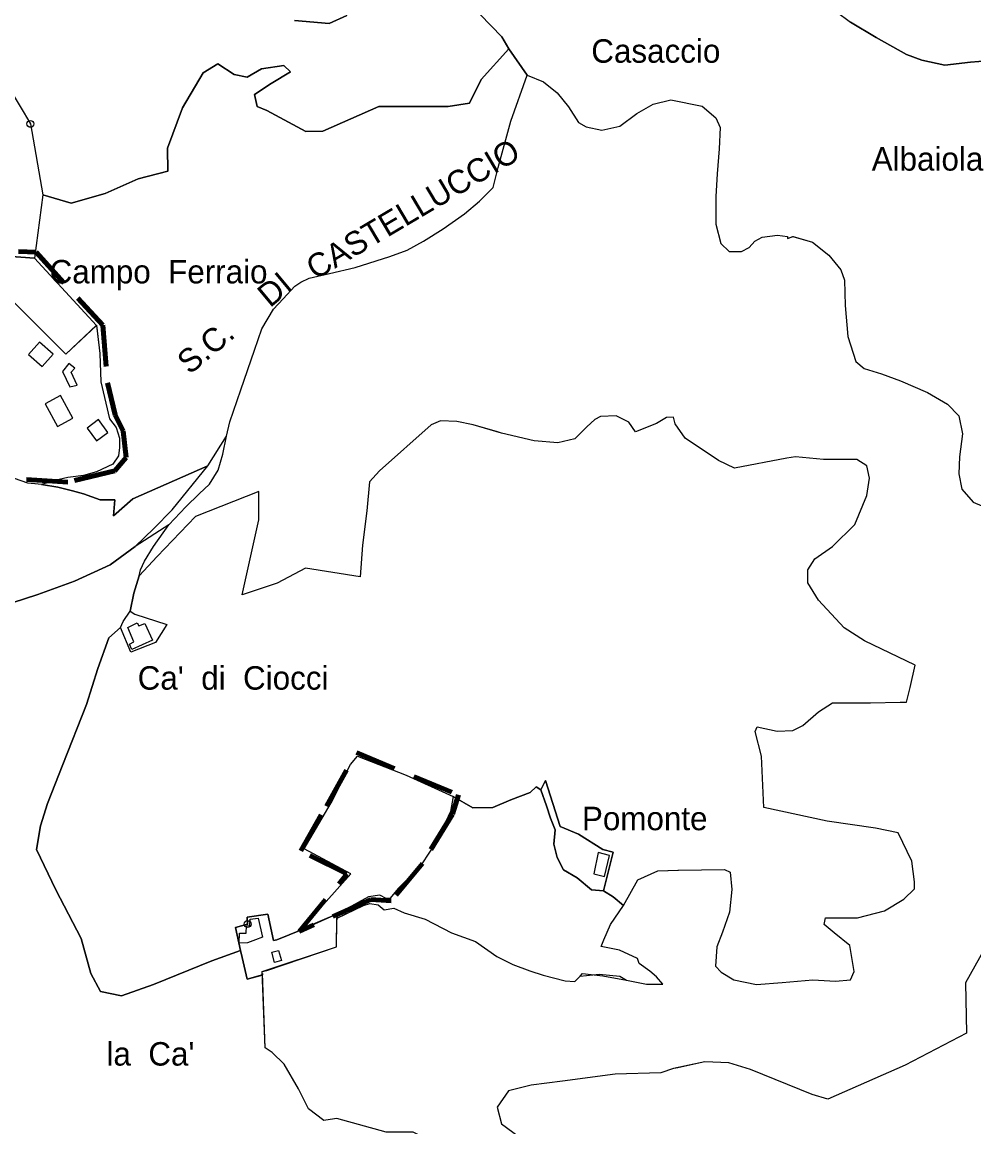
# Model space of a CAD drawing. Extents: x 645880 to 658994, y 884400 to 894744.
# Drawn here: x 654553 to 655242, y 890509 to 891309 of the extents above; entities that cross this region are included whole.
import ezdxf
from ezdxf.enums import TextEntityAlignment as Align

# ---------------------------------------------------------------- set-up
doc = ezdxf.new("R2010")
doc.units = 0
doc.header["$LTSCALE"] = 10
doc.header["$PDMODE"] = 32
doc.header["$PDSIZE"] = 5
doc.linetypes.add('MEDIUM_DASHED', pattern=[4.5, 3, -1.5])
for name, color, linetype, lineweight in [('15', 7, 'MEDIUM_DASHED', 100), ('16', 7, 'Continuous', 25), ('17', 7, 'Continuous', 25), ('18', 7, 'Continuous', 25), ('2', 7, 'Continuous', 25), ('3', 7, 'Continuous', 25), ('30', 7, 'Continuous', 25), ('4', 7, 'Continuous', 25), ('7', 7, 'Continuous', 25), ('8', 7, 'Continuous', 25)]:
    doc.layers.add(name, color=color, linetype=linetype, lineweight=lineweight)
doc.layers.add('60', color=7, linetype='Continuous')

msp = doc.modelspace()

# ---------------------------------------------------------------- linework, layer by layer
at = {"layer": '15'}
msp.add_lwpolyline([(654505.1, 891145.4), (654562.68, 891142.53), (654611.14, 891089.57), (654614.38, 891047.92), (654619.93, 891024.78), (654625.94, 891012.74), (654627.9, 890993.78), (654619.79, 890984.06), (654585.76, 890975.95), (654538.33, 890978.79)], dxfattribs=at)
msp.add_lwpolyline([(654794.8, 890779.81), (654868.71, 890749.12), (654864.4, 890735.17), (654842.78, 890699.57), (654820, 890672.35), (654805.2, 890673.29), (654753.25, 890650.2), (654787.88, 890691.88), (654754.49, 890708.59), (654773.07, 890741.05)], close=True, dxfattribs=at)
at = {"layer": '16'}
for p, q in [((655239.85, 891280.32), (655221.19, 891278.25)), ((655055.24, 891239.99), (655058.34, 891232.99)), ((655056.27, 891199.48), (655055.24, 891182.98)), ((655058.85, 891148.98), (655065.04, 891142.98)), ((655125.23, 891149.86), (655137.09, 891140.36)), ((655137.08, 891140.36), (655145.84, 891129.86)), ((655145.85, 891129.86), (655148.43, 891122.36))]:
    msp.add_line(p, q, dxfattribs=at)
for points in [[(655164.06, 891433.48), (655158.92, 891426.56), (655159.27, 891416.79), (655159.98, 891403.66), (655161.58, 891396.56), (655158.92, 891390.88), (655152.78, 891382.66), (655147.26, 891373.67), (655141.04, 891363.3), (655136.19, 891352.92), (655134.81, 891332.18), (655136.88, 891323.88), (655142.41, 891316.97), (655152.78, 891309.36), (655171.44, 891298.3), (655193.55, 891285.85), (655204.61, 891281.71), (655221.19, 891278.25), (655239.85, 891280.32), (655257.81, 891281.71)], [(654750.02, 891310.44), (654775.04, 891308.28), (654787.79, 891314.04)], [(654884.53, 891314.79), (654900.33, 891298.77), (654905.34, 891290.03), (654918.64, 891270.99)], [(655193.55, 891285.85), (655171.44, 891298.3), (655152.78, 891309.36)], [(655221.19, 891278.25), (655204.61, 891281.71), (655193.55, 891285.86)], [(655270.05, 891275.86), (655278.72, 891277.92), (655257.82, 891281.71), (655239.85, 891280.33)], [(654918.63, 891270.99), (654930.49, 891265.99), (654940.28, 891257.99), (654948.53, 891247.99), (654955.75, 891236.49), (654961.42, 891233.49), (654972.76, 891230.99), (654985.64, 891233.99), (654998.02, 891242.99), (655009.87, 891249.99), (655022.76, 891252.99), (655045.44, 891248.49), (655055.23, 891239.99)], [(655058.33, 891232.99), (655057.81, 891217.49), (655056.26, 891199.48)], [(655055.23, 891182.98), (655055.23, 891162.98), (655058.84, 891148.98)], [(655065.03, 891142.98), (655073.79, 891142.98), (655079.46, 891145.98), (655083.58, 891150.48), (655088.74, 891153.48), (655100.08, 891154.98), (655107.2, 891153.87), (655107.24, 891152.46)], [(655107.25, 891152.46), (655111.2, 891153.99), (655125.23, 891149.86)], [(655148.42, 891122.36), (655148.93, 891103.85), (655150.99, 891081.35), (655156.66, 891063.34), (655162.85, 891058.34), (655175.22, 891054.34), (655189.14, 891049.34), (655208.73, 891040.84), (655223.17, 891032.34), (655231.41, 891023.84), (655233.99, 891010.83), (655231.93, 890994.33), (655231.41, 890981.83), (655233.48, 890970.83), (655241.73, 890961.33), (655257.19, 890954.82)], [(655113.12, 890994.3), (655106.8, 890993.37), (655068.73, 890986.12), (655057.28, 890991.55), (655033.16, 891007.85), (655025.93, 891018.11), (655024.72, 891022.93), (655019.57, 891022.86), (655012.35, 891018.36), (654997.14, 891012.35), (654992.3, 891019.4), (654983.02, 891023.9), (654971.68, 891023.4), (654967.56, 891021.4), (654961.89, 891015.9), (654953.12, 891007.4), (654940.75, 891004.4), (654923.74, 891005.9), (654900.03, 891011.4), (654897.08, 891012.26), (654879.41, 891017.4), (654867.55, 891019.9), (654855.7, 891020.4), (654849, 891017.4), (654811.63, 890984.15), (654804.41, 890976.15), (654802.35, 890955.14), (654799.26, 890930.14), (654797.48, 890907.3), (654757.9, 890913.55), (654737.4, 890902.69), (654712.08, 890894.24), (654724.14, 890948.56), (654724.14, 890969.08), (654678.31, 890950.97), (654650.58, 890922), (654637.48, 890907.88), (654633.67, 890895.42), (654630.79, 890882.47), (654634.36, 890880.23)], [(655197.2, 890701.14), (655187.41, 890721.64), (655170.91, 890725.14), (655135.86, 890730.14), (655089.98, 890740.14), (655088.44, 890777.14), (655083.8, 890795.15), (655085.28, 890798.45), (655099.71, 890795.45), (655111.05, 890795.95), (655118.27, 890799.45), (655129.61, 890809.45), (655139.92, 890815.95), (655167.24, 890815.95), (655188.89, 890816.45), (655193.53, 890816.45), (655196.11, 890826.95), (655199.72, 890843.28), (655163.12, 890860.78), (655148.17, 890870.28), (655129.61, 890890.29), (655121.88, 890902.79), (655121.88, 890912.29), (655127.03, 890920.29), (655139.92, 890929.29), (655155.9, 890945.29), (655164.66, 890966.3), (655166.73, 890978.8), (655164.66, 890987.8), (655157.45, 890992.3), (655148.17, 890992.3), (655133.22, 890992.3), (655113.12, 890994.3)], [(654659.02, 890945), (654634.42, 890929.27), (654616.49, 890915.96), (654590.58, 890904), (654564.01, 890894.36), (654545.41, 890888.38), (654525.81, 890881.73)], [(654630.79, 890882.47), (654633.67, 890895.42), (654637.48, 890907.88), (654638.33, 890912.42), (654641.33, 890918.53), (654647.92, 890929.29), (654659.02, 890945)], [(654710.89, 890636.37), (654690.19, 890628.81), (654647.8, 890611.64), (654624.58, 890603.56), (654609.44, 890606.59), (654602.38, 890619.72), (654595.31, 890644.97), (654577.15, 890680.32), (654563.02, 890709.6), (654566.04, 890726.77), (654571.09, 890742.93), (654582.19, 890771.21), (654599.35, 890814.63), (654607.43, 890840.89), (654615.5, 890863.1), (654623.81, 890870.61), (654625.79, 890874.88), (654630.79, 890882.47)], [(654634.36, 890880.23), (654657.35, 890872.73), (654649.35, 890859.72), (654631.37, 890852.72), (654623.81, 890870.61)], [(654623.81, 890870.61), (654615.5, 890863.1), (654607.43, 890840.89), (654599.35, 890814.63), (654582.19, 890771.21), (654571.09, 890742.93), (654566.04, 890726.77), (654563.02, 890709.6)], [(654790.56, 890771.3), (654795.65, 890777.25), (654830.98, 890763.4), (654864.93, 890747.95)], [(654755.13, 890651.77), (654790.78, 890692.08), (654756.97, 890710.19), (654776.6, 890743.36), (654790.56, 890771.3)], [(654920.82, 890751.04), (654925.17, 890755.02), (654928.59, 890752.77), (654931.89, 890759.67), (654942.38, 890726.17), (654955.87, 890720.67), (654973.39, 890709.56), (654980.89, 890707.55), (654973.86, 890679.66), (654980.82, 890675.37), (654988.43, 890669.13), (654998.74, 890687.63), (655013.18, 890694.13), (655027.82, 890694.62), (655028.12, 890694.63), (655061.63, 890695.13), (655065.75, 890693.13), (655066.79, 890680.63), (655065.24, 890664.13), (655060.08, 890649.63), (655055.96, 890639.13), (655054.93, 890625.13), (655059.05, 890620.63), (655068.33, 890615.13), (655084.83, 890611.63), (655103.38, 890613.13), (655125.55, 890615.13), (655142.04, 890614.13), (655152.87, 890615.13), (655155.45, 890621.13), (655152.35, 890640.13), (655141.01, 890649.13), (655133.8, 890655.13), (655134.83, 890660.13), (655158.02, 890660.13), (655177.61, 890665.13), (655191.53, 890673.63), (655199.26, 890681.13), (655199.26, 890686.13), (655197.2, 890701.14)], [(654864.93, 890747.95), (654863.01, 890737.12), (654856.42, 890723.07), (654849.23, 890709.76), (654840.28, 890696.23), (654825.02, 890681.39)], [(654928.59, 890752.77), (654925.17, 890755.02), (654920.82, 890751.04), (654906.7, 890745.6), (654893.66, 890740.16), (654879.17, 890739.8), (654864.93, 890747.95)], [(654864.93, 890747.95), (654879.17, 890739.8), (654893.66, 890740.16), (654906.7, 890745.6), (654920.82, 890751.04)], [(654988.43, 890669.13), (654980.82, 890675.37), (654973.86, 890679.66), (654965.07, 890680.35), (654954.82, 890689.1), (654944.87, 890694.83), (654940.35, 890703.88), (654937.94, 890713.54), (654938.84, 890723.8), (654935.53, 890732.25), (654932.51, 890741.3), (654928.59, 890752.77)], [(654563.02, 890709.6), (654577.15, 890680.32), (654595.31, 890644.97)], [(654825.02, 890681.39), (654819.29, 890674.44), (654819.29, 890674.44), (654816.36, 890674.07), (654816.36, 890674.07), (654816.36, 890674.07), (654816.36, 890674.07), (654811.86, 890676.4), (654803.55, 890675.31), (654781.19, 890663.07), (654780.94, 890659.9), (654799.86, 890669.07), (654804.54, 890670.44), (654810.54, 890669.57), (654815.04, 890665.78), (654821.93, 890666.96), (654829.47, 890663.64), (654844.54, 890659.11), (654863.83, 890649.15)], [(654863.83, 890649.15), (654881.02, 890642.82), (654896.65, 890631.98), (654897.08, 890631.77), (654908.08, 890626.26), (654908.1, 890626.25), (654920.46, 890621.72), (654930.11, 890618.4), (654946.09, 890614.48), (654953.02, 890613.88), (654956.94, 890617.8), (654958.75, 890619.61), (654973.5, 890618.11), (654990.63, 890614.8), (655005.1, 890612.08), (655016.86, 890612.08), (655012.33, 890617.21), (655007.51, 890621.44), (654999.67, 890626.87), (654998.47, 890630.49), (654985.5, 890636.53), (654972.24, 890639.24), (654974.05, 890644.07), (654978.87, 890655.24), (654988.43, 890669.13)], [(654647.8, 890611.64), (654690.19, 890628.81), (654710.87, 890636.36), (654707.15, 890652.98), (654716, 890655.49), (654715.63, 890660.5), (654730.66, 890662.69), (654734.86, 890643.59), (654737.18, 890644.15), (654755.16, 890651.37), (654774.25, 890659.95), (654781.19, 890663.07), (654755.13, 890651.77)], [(654595.31, 890644.97), (654602.38, 890619.72), (654609.44, 890606.59)], [(654972.05, 890449.74), (654960.71, 890438.74), (654933.91, 890430.74), (654919.47, 890440.74), (654899.88, 890442.74), (654882.36, 890444.74), (654866.89, 890454.74), (654851.43, 890474.74), (654846.27, 890499.75), (654835.96, 890504.75), (654816.38, 890504.75), (654780.74, 890514.57), (654775.74, 890513.89), (654771.32, 890513.15), (654760.15, 890521.7), (654752.92, 890536.17), (654742.41, 890553.92), (654733.87, 890562.47), (654728.62, 890565.76), (654726.69, 890619.72), (654726.69, 890618.67), (654715.69, 890615.67), (654711.99, 890631.37), (654710.89, 890636.37)], [(655253.17, 890643.11), (655236.29, 890612.93), (655236.93, 890576.38), (655192.43, 890553.3), (655136.39, 890528.56), (655125, 890531.94), (655080.38, 890550.04), (655064.71, 890554.87), (655047.31, 890555.75), (655027.82, 890551.45), (655024.87, 890550.8), (655024.63, 890550.75), (655015.35, 890547.75), (654982.36, 890546.75), (654944.21, 890541.75), (654921.53, 890538.75), (654905.04, 890534.75), (654896.79, 890522.75), (654899.88, 890510.75), (654916.38, 890498.75), (654935.97, 890489.75), (654953.49, 890476.74), (654966.9, 890460.74), (654972.05, 890449.74)], [(654609.44, 890606.59), (654624.58, 890603.56), (654647.8, 890611.64)]]:
    msp.add_lwpolyline(points, dxfattribs=at)
at = {"layer": '17'}
for points in [[(654618.78, 890951.44), (654632.76, 890963.84), (654687.23, 890987.78), (654700.71, 891009.29), (654703.03, 891019.55), (654711.13, 891042.82), (654721.02, 891071.62), (654726.42, 891087.04), (654734.82, 891101.29), (654741.72, 891108.86), (654750.11, 891117.88), (654754.61, 891120.79), (654760.61, 891123.69), (654775.3, 891127.19), (654793.89, 891131.48), (654819.14, 891139.48), (654831.52, 891143.98), (654843.37, 891150.48), (654857.81, 891159.48), (654873.27, 891170.48), (654884.09, 891179.48), (654893.89, 891189.48), (654897.5, 891203.98), (654906.78, 891237.49), (654918.63, 891270.99), (654905.34, 891290.03), (654885.3, 891267.67), (654876.78, 891250.5), (654861.25, 891248.23), (654821.17, 891248.23), (654811.15, 891248.23), (654770.51, 891230.24), (654758.26, 891229.99), (654729.98, 891245.31), (654722.97, 891248.23), (654720.96, 891256.97), (654732.99, 891264.75), (654747.01, 891273.27), (654742.26, 891278.02), (654725.97, 891275.44)], [(654725.97, 891275.44), (654715.76, 891269.51), (654706.26, 891271.27), (654694.51, 891279.02), (654683.89, 891272.53), (654668.86, 891247.25), (654657.83, 891218.09), (654658.25, 891201.21), (654636.79, 891195.73), (654612.74, 891185.04), (654588.25, 891178.19), (654567.65, 891184.07), (654561.56, 891138.28), (654606.47, 891089.55)], [(654606.47, 891089.55), (654608.81, 891069.11), (654609.6, 891048.6), (654616.01, 891021.7), (654620.66, 891015.42), (654623.21, 891007.73)], [(654623.21, 891007.73), (654623.21, 891001), (654622.44, 890995.01), (654618.32, 890989.02), (654606.51, 890983.48), (654597, 890980.74), (654585.68, 890979.24), (654577.17, 890977.29), (654566.65, 890974.25)], [(654564.01, 890894.36), (654590.58, 890904), (654616.49, 890915.96), (654634.42, 890929.27), (654648.04, 890942.23), (654661.33, 890955.86), (654687.23, 890987.78), (654632.76, 890963.84), (654618.78, 890951.44)], [(654618.78, 890951.44), (654619.87, 890963.09), (654609.15, 890963.09), (654596.96, 890967.45), (654589.14, 890969.64), (654578.59, 890972.18), (654566.65, 890974.25), (654556.73, 890975.16), (654547.16, 890978.61)], [(654566.65, 890974.25), (654578.59, 890972.18), (654589.14, 890969.64), (654596.96, 890967.45), (654609.15, 890963.09), (654619.87, 890963.09), (654618.78, 890951.44)], [(654463.65, 890829.7), (654487.17, 890857.21), (654491.14, 890861.52), (654498.61, 890867.81), (654506.8, 890873.26), (654523.46, 890881.28), (654545.41, 890888.38), (654564.01, 890894.36)]]:
    msp.add_lwpolyline(points, dxfattribs=at)
at = {"layer": '18'}
for points in [[(654558.82, 891422.97), (654547.79, 891403.53), (654543.78, 891387.98), (654539.99, 891369.33), (654535.77, 891360.76), (654522.74, 891368.54), (654511.72, 891380.2), (654494.99, 891387.59), (654458.99, 891391.09), (654462.99, 891383.59), (654465.62, 891367.56), (654472.64, 891339.37), (654480.74, 891328.55), (654495.69, 891321.87), (654509.71, 891295.63), (654520.55, 891274.47), (654543.6, 891260.86), (654558.63, 891235.59)], [(654558.63, 891235.59), (654567.65, 891184.07), (654588.25, 891178.19), (654612.74, 891185.04), (654636.79, 891195.73), (654658.25, 891201.21), (654657.83, 891218.09), (654668.86, 891247.25), (654683.89, 891272.53), (654694.51, 891279.02), (654706.26, 891271.27), (654715.76, 891269.51), (654725.97, 891275.44), (654742.26, 891278.02), (654747.01, 891273.27), (654732.99, 891264.75), (654720.96, 891256.97), (654722.97, 891248.23), (654729.98, 891245.31), (654758.26, 891229.99), (654770.51, 891230.24), (654811.15, 891248.23), (654821.17, 891248.23), (654861.25, 891248.23), (654876.78, 891250.5), (654885.3, 891267.67), (654905.34, 891290.03), (654900.33, 891298.77), (654884.53, 891314.79)], [(654787.79, 891314.04), (654775.04, 891308.28), (654750.02, 891310.44)], [(654659.02, 890945), (654671.32, 890958.09), (654680.91, 890967.4), (654688.41, 890974.38), (654694.71, 890984.56), (654698.01, 890996.2), (654700.71, 891009.29), (654703.03, 891019.55), (654711.13, 891042.82), (654721.02, 891071.62), (654726.42, 891087.04), (654734.82, 891101.29), (654741.72, 891108.86), (654750.11, 891117.88), (654754.61, 891120.79), (654760.61, 891123.69), (654775.3, 891127.19), (654793.89, 891131.48), (654819.14, 891139.48), (654831.52, 891143.98), (654843.37, 891150.48), (654857.81, 891159.48), (654873.27, 891170.48), (654884.09, 891179.48), (654893.89, 891189.48), (654897.5, 891203.98), (654906.78, 891237.49), (654918.63, 891270.99), (654930.49, 891265.99), (654940.28, 891257.99), (654948.53, 891247.99), (654955.75, 891236.49), (654961.42, 891233.49), (654972.76, 891230.99), (654985.64, 891233.99), (654998.02, 891242.99), (655009.87, 891249.99), (655022.76, 891252.99), (655045.44, 891248.49), (655055.23, 891239.99)], [(655055.23, 891239.99), (655058.33, 891232.99), (655057.81, 891217.49), (655056.26, 891199.48), (655055.23, 891182.98), (655055.23, 891162.98), (655058.84, 891148.98), (655065.03, 891142.98), (655073.79, 891142.98), (655079.46, 891145.98), (655083.58, 891150.48), (655088.74, 891153.48), (655100.08, 891154.98), (655107.2, 891153.87), (655107.24, 891152.46), (655111.19, 891153.99)], [(655111.19, 891153.99), (655125.22, 891149.86), (655137.08, 891140.36), (655145.84, 891129.86), (655148.42, 891122.36), (655148.93, 891103.85), (655150.99, 891081.35), (655156.66, 891063.34), (655162.85, 891058.34), (655175.22, 891054.34), (655189.14, 891049.34), (655208.73, 891040.84), (655223.17, 891032.34), (655231.41, 891023.84), (655233.99, 891010.83), (655231.93, 890994.33), (655231.41, 890981.83), (655233.48, 890970.83), (655241.73, 890961.33), (655257.19, 890954.82)], [(655113.12, 890994.3), (655106.8, 890993.37), (655068.73, 890986.12), (655057.28, 890991.55), (655033.16, 891007.85), (655025.93, 891018.11), (655024.72, 891022.93), (655019.57, 891022.86), (655012.35, 891018.36), (654997.14, 891012.35), (654992.3, 891019.4), (654983.02, 891023.9), (654971.68, 891023.4), (654967.56, 891021.4), (654961.89, 891015.9), (654953.12, 891007.4), (654940.75, 891004.4), (654923.74, 891005.9), (654900.03, 891011.4), (654879.41, 891017.4), (654867.55, 891019.9), (654855.7, 891020.4), (654849, 891017.4), (654811.63, 890984.15), (654804.41, 890976.15), (654802.35, 890955.14), (654799.26, 890930.14), (654797.48, 890907.3), (654757.9, 890913.55), (654737.4, 890902.69), (654712.08, 890894.24), (654724.14, 890948.56), (654724.14, 890969.08), (654678.31, 890950.97), (654650.58, 890922), (654637.48, 890907.88), (654638.33, 890912.42), (654641.33, 890918.53), (654647.92, 890929.29), (654659.02, 890945)], [(655167.24, 890815.95), (655188.89, 890816.45), (655193.53, 890816.45), (655196.11, 890826.95), (655199.72, 890843.28), (655163.12, 890860.78), (655148.17, 890870.28), (655129.61, 890890.29), (655121.88, 890902.79), (655121.88, 890912.29), (655127.03, 890920.29), (655139.92, 890929.29), (655155.9, 890945.29), (655164.66, 890966.3), (655166.73, 890978.8), (655164.66, 890987.8), (655157.45, 890992.3), (655148.17, 890992.3), (655133.22, 890992.3), (655113.12, 890994.3)], [(655013.18, 890694.13), (655028.12, 890694.63), (655061.63, 890695.13), (655065.75, 890693.13), (655066.79, 890680.63), (655065.24, 890664.13), (655060.08, 890649.63), (655055.96, 890639.13), (655054.93, 890625.13), (655059.05, 890620.63), (655068.33, 890615.13), (655084.83, 890611.63), (655103.38, 890613.13), (655125.55, 890615.13), (655142.04, 890614.13), (655152.87, 890615.13), (655155.45, 890621.13), (655152.35, 890640.13), (655141.01, 890649.13), (655133.8, 890655.13), (655134.83, 890660.13), (655158.02, 890660.13), (655177.61, 890665.13), (655191.53, 890673.63), (655199.26, 890681.13), (655199.26, 890686.13), (655197.2, 890701.14), (655187.41, 890721.64), (655170.91, 890725.14), (655135.86, 890730.14), (655089.98, 890740.14), (655088.44, 890777.14), (655083.8, 890795.15), (655085.28, 890798.45), (655099.71, 890795.45), (655111.05, 890795.95), (655118.27, 890799.45), (655129.61, 890809.45), (655139.92, 890815.95), (655167.24, 890815.95)], [(654760.15, 890521.7), (654752.92, 890536.17), (654742.41, 890553.92), (654733.87, 890562.47), (654728.62, 890565.76), (654726.64, 890621.12), (654780.47, 890639.07), (654780.54, 890659.71), (654799.86, 890669.07), (654804.54, 890670.44), (654810.54, 890669.57), (654815.04, 890665.78), (654821.93, 890666.96), (654829.47, 890663.64), (654844.54, 890659.11), (654863.83, 890649.15), (654881.02, 890642.82), (654896.65, 890631.98), (654908.1, 890626.25), (654920.46, 890621.72), (654930.11, 890618.4), (654946.09, 890614.48), (654953.02, 890613.88), (654956.94, 890617.8), (654970.86, 890619.24), (654985.61, 890617.74), (654990.63, 890614.8), (655005.1, 890612.08), (655016.86, 890612.08), (655012.33, 890617.21), (655007.51, 890621.44), (654999.67, 890626.87), (654998.47, 890630.49), (654985.5, 890636.53), (654972.24, 890639.24), (654974.05, 890644.07), (654978.87, 890655.24), (654988.43, 890669.13), (654998.74, 890687.63), (655013.18, 890694.13)], [(655253.17, 890643.11), (655236.29, 890612.93), (655236.93, 890576.38), (655192.43, 890553.3), (655136.39, 890528.56), (655125, 890531.94), (655080.38, 890550.04), (655064.71, 890554.87), (655047.31, 890555.75), (655024.63, 890550.75), (655015.35, 890547.75), (654982.36, 890546.75), (654944.21, 890541.75), (654921.53, 890538.75), (654905.04, 890534.75), (654896.79, 890522.75), (654899.88, 890510.75), (654916.38, 890498.75)], [(654816.38, 890504.75), (654780.74, 890514.57), (654775.74, 890513.89), (654771.32, 890513.15), (654760.15, 890521.7)]]:
    msp.add_lwpolyline(points, dxfattribs=at)
msp.add_point((654558.63, 891235.59), dxfattribs=at)
at = {"layer": '2'}
for points in [[(654631.37, 890852.72), (654623.81, 890870.61), (654625.79, 890874.88), (654630.79, 890882.47), (654634.36, 890880.23), (654657.35, 890872.73), (654649.35, 890859.72)], [(654629.22, 890870.52), (654635.99, 890873.83), (654637.25, 890871.78), (654641.5, 890873.51), (654647.17, 890861.23), (654632.13, 890854.53), (654630.34, 890858.5), (654633.5, 890860.19)]]:
    msp.add_lwpolyline(points, close=True, dxfattribs=at)
at = {"layer": '3'}
msp.add_line((654716, 890655.49), (654707.15, 890652.98), dxfattribs=at)
msp.add_lwpolyline([(654707.15, 890652.98), (654710.87, 890636.35), (654712.01, 890631.4), (654715.65, 890615.62), (654726.64, 890618.62), (654726.64, 890621.12), (654729.89, 890621.97), (654780.47, 890639.07), (654780.68, 890656.84), (654781.19, 890663.07), (654774.25, 890659.95), (654755.16, 890651.37), (654737.18, 890644.15), (654734.86, 890643.59), (654730.66, 890662.69), (654715.63, 890660.5), (654716, 890655.49)], dxfattribs=at)
for points in [[(654717.79, 890659.08), (654723.75, 890659.91), (654726.87, 890646.11), (654721.74, 890644.06), (654716.01, 890641.94), (654709.85, 890641.78), (654710.02, 890648.87), (654715.04, 890648.87), (654715.2, 890654.22), (654717.6, 890654.4)], [(654733.51, 890635.09), (654738.36, 890636.5), (654740.5, 890629.06), (654735.48, 890627.63)]]:
    msp.add_lwpolyline(points, close=True, dxfattribs=at)
msp.add_point((654716, 890655.49), dxfattribs=at)
at = {"layer": '30'}
msp.add_lwpolyline([(654461.79, 891182.86), (654462.45, 891186.3), (654462.95, 891192.7), (654463.75, 891207.08), (654463.57, 891216.28), (654463.2, 891221.42), (654462.07, 891228.32), (654457.27, 891245.62), (654451.54, 891266.83), (654449.06, 891280.54), (654448.15, 891286.34), (654508.46, 891297.97), (654520.55, 891274.47), (654543.6, 891260.86), (654558.63, 891235.59), (654567.65, 891184.07), (654567.65, 891184.07), (654561.56, 891138.28), (654498.47, 891142.75), (654500.29, 891182.02), (654465.9, 891183.04)], close=True, dxfattribs=at)
at = {"layer": '4'}
for points in [[(654931.89, 890759.67), (654928.59, 890752.77), (654932.51, 890741.3), (654935.53, 890732.25), (654938.84, 890723.8), (654937.94, 890713.54), (654940.35, 890703.88), (654944.87, 890694.83), (654954.82, 890689.1), (654965.07, 890680.35), (654973.86, 890679.66), (654980.89, 890707.55), (654973.39, 890709.56), (654955.87, 890720.67), (654942.38, 890726.17)], [(654970.1, 890707.4), (654966.8, 890692.01), (654974.7, 890690.14), (654978.29, 890705.3)]]:
    msp.add_lwpolyline(points, close=True, dxfattribs=at)
at = {"layer": '7'}
for points in [[(654565.22, 891077.38), (654557.26, 891068.33), (654567.09, 891059.68), (654575.05, 891068.73)], [(654586.44, 891061.99), (654581.77, 891056.14), (654587.26, 891044.96), (654592.47, 891046.29), (654588.08, 891055.61), (654590.83, 891058.53)], [(654580.5, 891038.73), (654569.25, 891032.62), (654578.17, 891016.2), (654589.42, 891022.31)], [(654607.92, 891021.18), (654599.69, 891015.06), (654606.55, 891005.84), (654614.78, 891011.97)]]:
    msp.add_lwpolyline(points, close=True, dxfattribs=at)
at = {"layer": '8'}
msp.add_lwpolyline([(654498.47, 891142.75), (654561.56, 891138.28), (654606.48, 891089.53), (654584.34, 891068.6), (654539.46, 891113.62), (654497.08, 891118.13)], close=True, dxfattribs=at)
for points in [[(654539.46, 891113.62), (654584.34, 891068.6), (654606.46, 891089.58), (654608.81, 891069.11), (654609.6, 891048.6), (654616.01, 891021.7), (654620.66, 891015.42), (654623.21, 891007.73), (654623.21, 891001), (654622.44, 890995.01), (654618.32, 890989.02), (654606.51, 890983.48), (654597, 890980.74), (654585.68, 890979.24), (654577.17, 890977.29), (654566.65, 890974.25), (654562.1, 890974.69), (654556.73, 890975.16), (654547.16, 890978.61)], [(654790.56, 890771.3), (654795.65, 890777.25), (654830.98, 890763.4), (654864.93, 890747.95), (654863.01, 890737.12), (654856.42, 890723.07), (654849.23, 890709.76), (654840.28, 890696.23), (654825.02, 890681.39)], [(654755.13, 890651.77), (654790.78, 890692.08), (654756.97, 890710.19), (654776.6, 890743.36), (654790.56, 890771.3)], [(654825.02, 890681.39), (654819.29, 890674.44), (654819.29, 890674.44), (654816.36, 890674.07), (654816.36, 890674.07), (654816.36, 890674.07), (654816.36, 890674.07), (654811.86, 890676.4), (654803.55, 890675.31), (654781.19, 890663.07), (654755.13, 890651.77)]]:
    msp.add_lwpolyline(points, dxfattribs=at)

# ---------------------------------------------------------------- texts
at = {"layer": '60'}
for s, p in [('Casaccio', (655011.8, 891279.91)), ('Albaiola', (655208.67, 891201.71)), ('Campo  Ferraio', (654651.47, 891119.95)), ("Ca'  di  Ciocci", (654705.46, 890825.46)), ('Pomonte', (655003.76, 890723.59)), ("la  Ca'", (654645.6, 890552.97))]:
    msp.add_text(s, height=17, dxfattribs=at).set_placement(p, align=Align.CENTER)
for s, rotation, p in [('CASTELLUCCIO', 30.656, (654840.04, 891166.62)), ('S.C.     DI', 39.809, (654711.84, 891084.9))]:
    msp.add_text(s, height=17, rotation=rotation, dxfattribs=at).set_placement(p, align=Align.CENTER)

doc.saveas('drawing.dxf')
